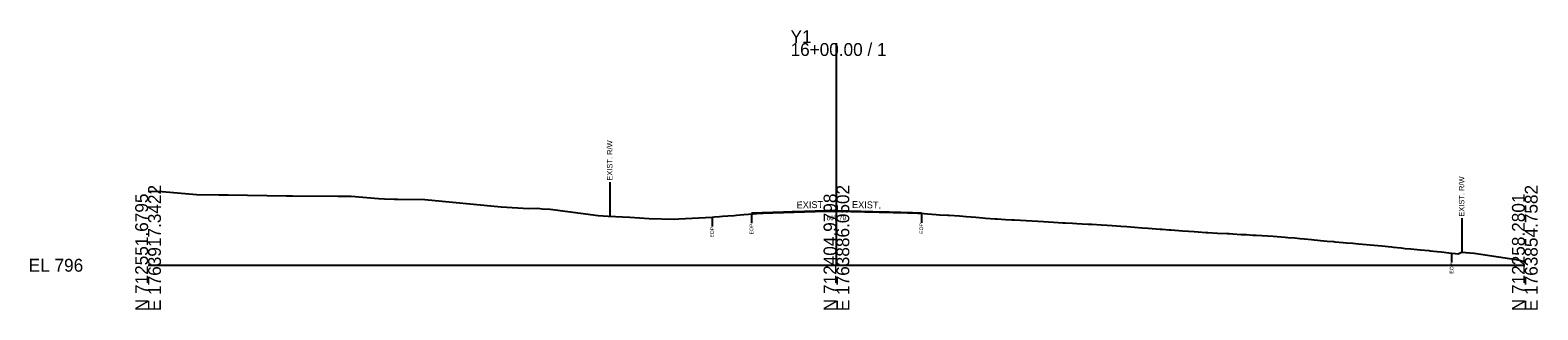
# Model space of a CAD drawing. Extents: x -26 to 1303, y -10 to 9524.
# Drawn here: x -25.7 to 302.8, y 5990.3 to 6051.2 of the extents above; entities that cross this region are included whole.
import ezdxf

# ---------------------------------------------------------------- set-up
doc = ezdxf.new("R2010")
doc.units = 0
for name, color, linetype in [('Default', 7, 'Continuous'), ('Exist Cross Section Cell', 7, 'Continuous'), ('Exist XS Center Line Elevation Label', 7, 'Continuous'), ('Exist XS Ground Line', 7, 'Continuous'), ('Old_Level_10', 7, 'Continuous'), ('Prop CMT Pvmt Surface Overlay', 7, 'Continuous'), ('Prop XS SE Text', 7, 'Continuous')]:
    doc.layers.add(name, color=color, linetype=linetype)

msp = doc.modelspace()

# ---------------------------------------------------------------- linework, layer by layer
at = {"layer": 'Exist Cross Section Cell'}
for p, q in [((150, 6000), (150, 6048.35)), ((0, 6000), (150, 6000)), ((150, 6000), (300, 6000))]:
    msp.add_line(p, q, dxfattribs=at)
at = {"layer": 'Exist XS Ground Line'}
msp.add_lwpolyline([(0, 6016.12), (3.04, 6016.05), (10.54, 6015.41), (15.42, 6015.35), (17.44, 6015.32), (30.15, 6015.12), (31.5, 6015.13), (41.34, 6015.04), (44.29, 6015.01), (50.23, 6014.52), (51.5, 6014.49), (53.67, 6014.41), (54.4, 6014.4), (60.29, 6014.28), (76.94, 6012.72), (82.98, 6012.33), (84.93, 6012.39), (85.87, 6012.31), (87.65, 6012.18), (98.09, 6010.85), (100.26, 6010.71), (105, 6010.49), (109.16, 6010.14), (114.65, 6010), (115.67, 6010.08), (122.89, 6010.49), (123.43, 6010.53), (124.51, 6010.62), (125.17, 6010.67), (126.32, 6010.75), (127.69, 6010.86), (128.25, 6010.9), (129.8, 6011.03), (130.81, 6011.12), (131.91, 6011.22), (133.36, 6011.31), (134.01, 6011.36), (135.92, 6011.5), (137.06, 6011.58), (138.48, 6011.66), (140.33, 6011.69), (141.03, 6011.7), (142.44, 6011.71), (143.59, 6011.73), (144.55, 6011.75), (146.14, 6011.77), (146.65, 6011.77), (149.04, 6011.78), (150, 6011.79), (150.87, 6011.8), (151.26, 6011.8), (151.86, 6011.79), (153.81, 6011.77), (155.08, 6011.75), (156.37, 6011.72), (158.36, 6011.66), (158.93, 6011.65), (159.3, 6011.64), (161.03, 6011.64), (161.48, 6011.64), (163.51, 6011.58), (164.04, 6011.57), (165.62, 6011.5), (166.59, 6011.46), (167.72, 6011.37), (169.15, 6011.26), (169.83, 6011.21), (171.75, 6011.07), (172.48, 6011), (174.26, 6010.91), (174.6, 6010.89), (176.82, 6010.72), (178.26, 6010.61), (179.38, 6010.52), (180.36, 6010.43), (181.93, 6010.32), (182.47, 6010.28), (184.58, 6010.13), (184.99, 6010.11), (186.85, 6009.99), (188.24, 6009.9), (188.79, 6009.87), (190.11, 6009.78), (195.15, 6009.49), (197.27, 6009.36), (199.33, 6009.24), (199.83, 6009.22), (201.43, 6009.13), (202.38, 6009.08), (203.54, 6009.03), (204.94, 6008.95), (205.65, 6008.93), (207.75, 6008.81), (208.96, 6008.73), (210.05, 6008.65), (211.97, 6008.51), (213.31, 6008.42), (216.64, 6008.15), (217.91, 6008.05), (220.53, 6007.85), (220.95, 6007.82), (222.5, 6007.7), (222.83, 6007.68), (224.61, 6007.56), (225.39, 6007.5), (226.71, 6007.4), (227.94, 6007.32), (228.82, 6007.26), (230.5, 6007.16), (230.93, 6007.14), (233.06, 6007.02), (235.14, 6006.9), (235.61, 6006.88), (236.34, 6006.83), (238.17, 6006.73), (239.36, 6006.66), (240.73, 6006.57), (241.46, 6006.52), (245.15, 6006.3), (247.78, 6006.12), (248.39, 6006.06), (249.89, 6005.97), (250.95, 6005.85), (252, 6005.76), (253.51, 6005.58), (254.1, 6005.53), (256.21, 6005.32), (256.9, 6005.26), (258.32, 6005.14), (258.62, 6005.11), (260.42, 6004.97), (261.18, 6004.9), (262.53, 6004.79), (263.73, 6004.68), (264.64, 6004.61), (266.29, 6004.45), (268.88, 6004.22), (270.96, 6004), (271.4, 6003.96), (273.06, 6003.78), (273.96, 6003.68), (275.17, 6003.57), (276.51, 6003.45), (277.28, 6003.38), (279.07, 6003.2), (279.39, 6003.16), (280.87, 6003), (281.79, 6002.9), (284.05, 6002.64), (284.93, 6002.53), (285.5, 6002.47), (286.21, 6002.85), (288.99, 6002.64), (298.11, 6001.27), (300, 6000.79)], dxfattribs=at)
at = {"layer": 'Old_Level_10'}
for p, q in [((100.6, 6018.1), (100.6, 6010.7)), ((122.89, 6010.49), (122.89, 6008.44)), ((131.48, 6011.18), (131.48, 6009.13)), ((168.5, 6011.31), (168.5, 6009.26)), ((286.24, 6010.25), (286.24, 6002.85)), ((284.05, 6002.64), (284.05, 6000.59))]:
    msp.add_line(p, q, dxfattribs=at)
at = {"layer": 'Prop CMT Pvmt Surface Overlay'}
for p, q in [((150, 6011.92), (131.48, 6011.31)), ((150, 6011.79), (131.48, 6011.18)), ((150, 6011.92), (168.54, 6011.43)), ((150, 6011.79), (168.54, 6011.31))]:
    msp.add_line(p, q, dxfattribs=at)

# ---------------------------------------------------------------- texts
at = {"layer": 'Default'}
msp.add_text('-', height=0.0001, dxfattribs=at).set_placement((0, 6000))
at = {"layer": 'Exist Cross Section Cell'}
for s, p in [('Y1', (140, 6048.35)), ('16+00.00 / 1', (140, 6045.55)), ('EL 796', (-26, 5998.6))]:
    msp.add_text(s, height=2.8, dxfattribs=at).set_placement(p)
for s, p in [('N 712551.6795', (0, 5990)), ('E 1763917.3422', (2.8, 5990)), ('N 712404.9798', (150, 5990)), ('E 1763886.0502', (152.8, 5990)), ('E 1763854.7582', (302.8, 5990)), ('N 712258.2801', (300, 5990))]:
    msp.add_text(s, height=2.8, rotation=90, dxfattribs=at).set_placement(p)
at = {"layer": 'Exist XS Center Line Elevation Label'}
msp.add_text('807.79', height=1, dxfattribs=at).set_placement((147.87, 6009.79))
at = {"layer": 'Old_Level_10'}
for s, height, p in [('EXIST. R/W', 1.181, (101.19, 6018.4)), ('EXIST. R/W', 1.181, (286.83, 6010.55)), ('EOP', 0.787, (131.87, 6006.73)), ('EOP', 0.787, (168.89, 6006.86)), ('EOP', 0.787, (123.28, 6006.04)), ('EOP', 0.787, (284.44, 5998.19))]:
    msp.add_text(s, height=height, rotation=90, dxfattribs=at).set_placement(p)
at = {"layer": 'Prop XS SE Text'}
for rotation, p in [(1.1458, (141.33, 6012.36)), (358.8542, (153.37, 6012.47))]:
    msp.add_text('EXIST.', height=1.5, rotation=rotation, dxfattribs=at).set_placement(p)

doc.saveas('drawing.dxf')
